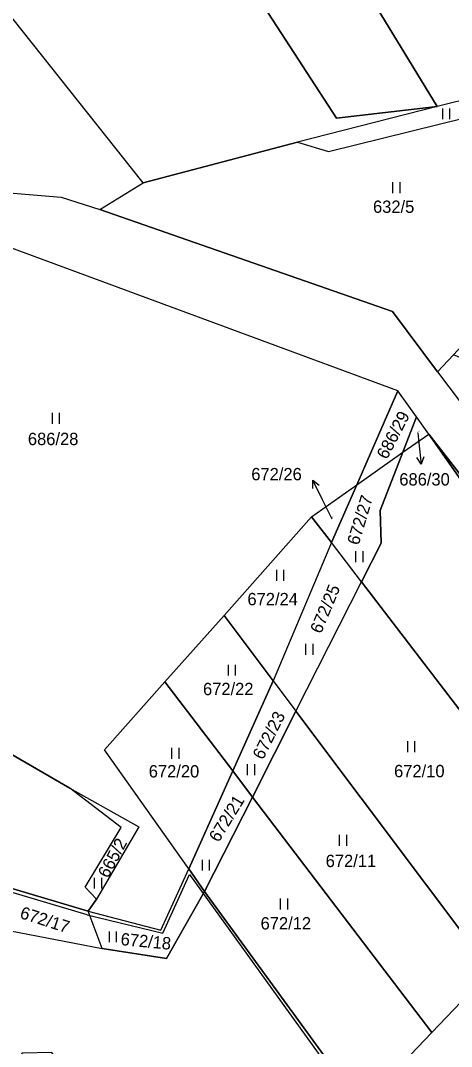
# Model space of a CAD drawing. Extents: x -654083 to -650132, y -1099819 to -1096699.
# Drawn here: x -651993.4 to -651934, y -1099122.2 to -1098980.8 of the extents above; entities that cross this region are included whole.
import ezdxf

# ---------------------------------------------------------------- set-up
doc = ezdxf.new("R2010")
doc.units = 0
for name, color, linetype in [('Obvody jako plochy', 7, 'Continuous'), ('Ostatní hranice', 7, 'Continuous'), ('Parcelní čísla', 7, 'Continuous'), ('Prvky pro prodl_ par_ č_', 7, 'Continuous'), ('Značky kultur', 7, 'Continuous')]:
    doc.layers.add(name, color=color, linetype=linetype)

msp = doc.modelspace()

# ---------------------------------------------------------------- linework, layer by layer
at = {"layer": 'Obvody jako plochy'}
for points in [[(-651939.84, -1098926.87), (-651907.33, -1098978.84), (-651913.06, -1098981.68), (-651917.75, -1098984.88), (-651921.86, -1098988.27), (-651930.47, -1098991.27), (-651935.99, -1098992.68), (-651977.57, -1098924.42), (-652012.77, -1098870.4), (-651989.91, -1098856.67), (-651988.2, -1098855.79)], [(-652012.77, -1098870.4), (-651977.57, -1098924.42), (-651935.99, -1098992.68), (-651949.86, -1098994.27), (-652024.84, -1098878.82)], [(-651935.99, -1098992.68), (-651955.22, -1098997.58), (-651976.47, -1099003.17), (-652051.48, -1098908.71), (-652044.25, -1098897.77), (-652024.84, -1098878.82), (-651949.86, -1098994.27)], [(-651982.47, -1099006.86), (-651976.47, -1099003.17), (-652051.48, -1098908.71), (-652067.69, -1098930.81), (-652069.7, -1098932.89), (-652071.78, -1098939.34), (-652068.19, -1098944.43), (-652067.27, -1098951.96), (-652048.76, -1098968.58), (-652035.5, -1098987.36), (-652018.55, -1098998.86), (-652003.18, -1099003.88), (-651987.76, -1099005.15)], [(-651953.3, -1099049.2), (-651947.09, -1099044.82), (-651941.44, -1099031.87), (-652020.94, -1099002.46), (-652036.36, -1098991.75), (-652052.55, -1098970.01), (-652066.5, -1098955.88), (-652066.71, -1098985.91), (-652065.03, -1098990.08), (-652046.44, -1099028.6), (-652014.51, -1099048.85), (-652013.9, -1099053.95), (-652011.91, -1099055.96), (-652006.08, -1099075.31), (-651986.57, -1099086.63), (-651977.08, -1099091.95), (-651982.9, -1099101.91), (-651984.07, -1099103.58), (-651974.07, -1099106.19), (-651970.21, -1099097.74), (-651981.79, -1099081.32), (-651973.49, -1099071.96), (-651965.35, -1099062.79)], [(-651916.97, -1098990.46), (-651917.75, -1098984.88), (-651921.86, -1098988.27), (-651930.47, -1098991.27), (-651935.99, -1098992.68), (-651955.22, -1098997.58), (-651950.95, -1098998.88)], [(-652018.06, -1099050.23), (-652036.49, -1099041.41), (-652045.75, -1099033.01), (-652050.08, -1099027.22), (-652065.03, -1098990.08), (-652076.34, -1099006.56), (-652065.41, -1099017.14), (-652070.24, -1099025.48), (-652067.23, -1099028.19), (-652091.89, -1099078.52), (-652094.79, -1099085.04), (-652084.82, -1099085.58), (-652070.9, -1099086.07), (-652068.94, -1099082.5), (-652065.81, -1099076.6), (-652052.39, -1099083.22), (-651984.07, -1099103.58), (-651982.9, -1099101.91), (-651984.49, -1099100.24), (-651979.53, -1099092.02), (-651986.57, -1099086.63), (-652006.08, -1099075.31), (-652011.91, -1099055.96), (-652013.9, -1099053.95)], [(-651916.97, -1098990.46), (-651914.16, -1099005.5), (-651922.23, -1099014.41), (-651933.77, -1099026.87), (-651935.95, -1099029.24), (-651942.14, -1099020.9), (-651982.47, -1099006.86), (-651976.47, -1099003.17), (-651955.22, -1098997.58), (-651950.95, -1098998.88)], [(-651905.62, -1099038.66), (-651908.3, -1099037.53), (-651933.77, -1099026.87), (-651935.95, -1099029.24), (-651895.45, -1099082.92), (-651882.03, -1099068.39), (-651885.66, -1099063.3), (-651901.49, -1099062.58), (-651908.94, -1099060.74), (-651908.24, -1099049.35)], [(-651940.73, -1099040.32), (-651938.83, -1099035.42), (-651941.44, -1099031.87), (-651947.09, -1099044.82)], [(-651940.73, -1099040.32), (-651937.17, -1099037.81), (-651938.83, -1099035.42)], [(-651937.17, -1099037.81), (-651903.83, -1099085.44), (-651915.71, -1099098.28), (-651946.43, -1099058.17), (-651943.73, -1099052.83), (-651943.84, -1099048.35), (-651940.73, -1099040.32)], [(-651895.32, -1099091.67), (-651897.34, -1099093.49), (-651903.83, -1099085.44), (-651937.17, -1099037.81)], [(-651947.09, -1099044.82), (-651940.73, -1099040.32), (-651943.84, -1099048.35), (-651943.73, -1099052.83), (-651946.43, -1099058.17), (-651950.56, -1099052.77)], [(-651947.09, -1099044.82), (-651950.56, -1099052.77), (-651953.3, -1099049.2)], [(-651953.3, -1099049.2), (-651950.56, -1099052.77), (-651958.57, -1099071.8), (-651965.35, -1099062.79)], [(-651955.45, -1099076), (-651946.43, -1099058.17), (-651950.56, -1099052.77), (-651958.57, -1099071.8)], [(-651946.43, -1099058.17), (-651915.71, -1099098.28), (-651928.62, -1099111.78), (-651955.45, -1099076)], [(-651958.57, -1099071.8), (-651964.15, -1099084.24), (-651973.49, -1099071.96), (-651965.35, -1099062.79)], [(-651964.15, -1099084.24), (-651970.21, -1099097.74), (-651981.79, -1099081.32), (-651973.49, -1099071.96)], [(-651958.57, -1099071.8), (-651955.45, -1099076), (-651961.43, -1099087.83), (-651964.15, -1099084.24)], [(-651955.45, -1099076), (-651928.62, -1099111.78), (-651936.76, -1099120.3), (-651961.43, -1099087.83)], [(-651982.14, -1099108.69), (-651984.07, -1099103.58), (-652052.39, -1099083.22), (-651997.42, -1099105.77)], [(-651964.15, -1099084.24), (-651961.43, -1099087.83), (-651968.03, -1099100.87), (-651970.21, -1099097.74)], [(-651913.47, -1099113.68), (-651915.2, -1099112.22), (-651911.37, -1099106.96), (-651909.45, -1099108.15), (-651897.34, -1099093.49), (-651903.83, -1099085.44), (-651915.71, -1099098.28), (-651928.62, -1099111.78), (-651936.76, -1099120.3), (-651946.49, -1099130.48), (-651938.16, -1099141.93), (-651935.02, -1099139.34), (-651930.53, -1099135.13), (-651926.34, -1099130.8), (-651921.46, -1099123.99)], [(-651977.08, -1099091.95), (-651982.9, -1099101.91), (-651984.49, -1099100.24), (-651979.53, -1099092.02), (-651986.57, -1099086.63)], [(-651961.43, -1099087.83), (-651936.76, -1099120.3), (-651946.49, -1099130.48), (-651968.03, -1099100.87)], [(-651970.21, -1099097.74), (-651968.03, -1099100.87), (-651973.27, -1099110.1), (-651982.14, -1099108.69), (-651984.07, -1099103.58), (-651974.07, -1099106.19)]]:
    msp.add_lwpolyline(points, close=True, dxfattribs=at)
for points in [[(-652048.76, -1098968.58), (-652035.5, -1098987.36), (-652018.55, -1098998.86), (-652003.18, -1099003.88), (-651987.76, -1099005.15), (-651982.47, -1099006.86), (-651942.14, -1099020.9), (-651935.95, -1099029.24), (-651895.45, -1099082.92), (-651891.04, -1099089.43), (-651887.81, -1099092.75), (-651872, -1099104.86), (-651875.74, -1099109.58), (-651881.55, -1099105.02), (-651895.32, -1099091.67), (-651937.17, -1099037.81), (-651938.83, -1099035.42), (-651941.44, -1099031.87), (-652020.94, -1099002.46), (-652036.36, -1098991.75), (-652052.55, -1098970.01)], [(-651997.42, -1099105.77), (-651982.14, -1099108.69), (-651973.27, -1099110.1), (-651968.03, -1099100.87), (-651946.49, -1099130.48), (-651938.16, -1099141.93), (-651938.71, -1099142.29), (-651943.03, -1099138.95), (-651945.28, -1099141.45), (-651947.36, -1099139.73), (-651953.83, -1099145.88), (-651964.62, -1099156.06), (-651980.39, -1099128.55), (-651985.16, -1099128.75), (-651989.08, -1099123.03), (-651993.14, -1099123.13), (-652100.46, -1099256.77)]]:
    msp.add_lwpolyline(points, dxfattribs=at)
at = {"layer": 'Ostatní hranice'}
for p, q in [((-651984.2, -1099104.06), (-652052.58, -1099083.68)), ((-651973.79, -1099106.6), (-651970.11, -1099098.51)), ((-651970.11, -1099098.51), (-651946.88, -1099130.79)), ((-651984.2, -1099104.06), (-651973.79, -1099106.6))]:
    msp.add_line(p, q, dxfattribs=at)
at = {"layer": 'Prvky pro prodl_ par_ č_'}
for p, q in [((-651938.69, -1099037.65), (-651938.54, -1099039)), ((-651938.54, -1099039), (-651938.2, -1099041.98)), ((-651951.79, -1099046.86), (-651953.14, -1099044.18)), ((-651950.45, -1099049.54), (-651951.79, -1099046.86))]:
    msp.add_line(p, q, dxfattribs=at)
for points in [[(-651937.82, -1099040.93), (-651938.2, -1099041.98), (-651938.81, -1099041.04)], [(-651953.13, -1099045.3), (-651953.14, -1099044.18), (-651952.24, -1099044.85)]]:
    msp.add_lwpolyline(points, dxfattribs=at)
at = {"layer": 'Značky kultur'}
for p, q in [((-651935.29, -1098992.93), (-651935.29, -1098994.43)), ((-651934.27, -1098994.43), (-651934.27, -1098992.93)), ((-651942.14, -1099003.11), (-651942.14, -1099004.61)), ((-651941.11, -1099004.61), (-651941.11, -1099003.11)), ((-651989.03, -1099034.9), (-651989.03, -1099036.4)), ((-651988.01, -1099036.4), (-651988.01, -1099034.9)), ((-651947.23, -1099053.96), (-651947.23, -1099055.46)), ((-651946.2, -1099055.46), (-651946.2, -1099053.96)), ((-651958.14, -1099056.53), (-651958.14, -1099058.03)), ((-651957.11, -1099058.03), (-651957.11, -1099056.53)), ((-651954.13, -1099066.73), (-651954.13, -1099068.23)), ((-651953.1, -1099068.23), (-651953.1, -1099066.73)), ((-651964.8, -1099069.6), (-651964.8, -1099071.1)), ((-651963.78, -1099071.1), (-651963.78, -1099069.6)), ((-651940.1, -1099080.14), (-651940.1, -1099081.64)), ((-651939.08, -1099081.64), (-651939.08, -1099080.14)), ((-651972.57, -1099081.05), (-651972.57, -1099082.55)), ((-651971.55, -1099082.55), (-651971.55, -1099081.05)), ((-651962.15, -1099083.31), (-651962.15, -1099084.81)), ((-651961.12, -1099084.81), (-651961.12, -1099083.31)), ((-651949.49, -1099093.06), (-651949.49, -1099094.56)), ((-651948.46, -1099094.56), (-651948.46, -1099093.06)), ((-651968.38, -1099096.47), (-651968.38, -1099097.97)), ((-651967.35, -1099097.97), (-651967.35, -1099096.47)), ((-651983.22, -1099098.95), (-651983.22, -1099100.45)), ((-651982.2, -1099100.45), (-651982.2, -1099098.95)), ((-651957.62, -1099101.83), (-651957.62, -1099103.33)), ((-651956.59, -1099103.33), (-651956.59, -1099101.83)), ((-651981.17, -1099106.34), (-651981.17, -1099107.84)), ((-651980.15, -1099107.84), (-651980.15, -1099106.34))]:
    msp.add_line(p, q, dxfattribs=at)

# ---------------------------------------------------------------- texts
at = {"layer": 'Parcelní čísla'}
for s, p in [('632/5', (-651944.84, -1099007.33)), ('686/28', (-651992.36, -1099039.33)), ('672/24', (-651962.13, -1099061.4)), ('672/22', (-651968.25, -1099073.79)), ('672/20', (-651975.72, -1099085.13)), ('672/10', (-651941.94, -1099085.1)), ('672/11', (-651951.36, -1099097.48)), ('672/12', (-651960.32, -1099106.08))]:
    msp.add_text(s, height=1.7, dxfattribs=at).set_placement(p)
for s, height, rotation, p in [('686/29', 1.7, 62.487, (-651942.93, -1099041.41)), ('686/30', 0.1, 39.177, (-651938.69, -1099037.65)), ('672/27', 1.7, 73.224, (-651946.83, -1099053.22)), ('672/26', 0.1, 62.298, (-651950.45, -1099049.54)), ('672/25', 1.7, 67.302, (-651952, -1099065.42)), ('672/23', 1.7, 63.333, (-651959.99, -1099082.8)), ('672/21', 1.7, 58.356, (-651966.1, -1099094.18)), ('665/2', 1.7, 61.722, (-651981.33, -1099099.12)), ('672/17', 1.7, 342.117, (-651993.58, -1099104.48)), ('672/18', 1.7, 354.564, (-651979.65, -1099108.22))]:
    msp.add_text(s, height=height, rotation=rotation, dxfattribs=at).set_placement(p)
at = {"layer": 'Prvky pro prodl_ par_ č_'}
for s, p in [('672/26', (-651961.6, -1099044.18)), ('686/30', (-651941.22, -1099044.9))]:
    msp.add_text(s, height=1.7, dxfattribs=at).set_placement(p)

doc.saveas('drawing.dxf')
